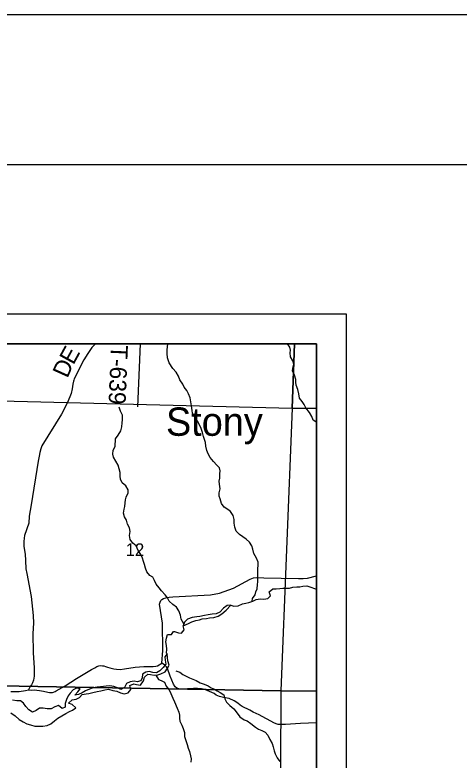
# Model space of a CAD drawing. Extents: x -7.1 to 34, y 0 to 22.
# Drawn here: x 7.891 to 9.377, y 19.508 to 22 of the extents above; entities that cross this region are included whole.
import ezdxf

# ---------------------------------------------------------------- set-up
doc = ezdxf.new("R2010")
doc.units = 0
for name, color, linetype in [('Default', 7, 'Continuous'), ('GM_X_County_Road', 7, 'Continuous'), ('GM_X_Major_Lake', 7, 'Continuous'), ('GM_X_Major_River', 7, 'Continuous'), ('GM_X_Minor_Lake_Text', 7, 'Continuous'), ('GM_X_Minor_River', 7, 'Continuous'), ('GM_X_Section', 7, 'Continuous'), ('GM_X_Section_Text', 7, 'Continuous'), ('GM_X_Township_Road', 7, 'Continuous'), ('GM_X_Township_Road_Text', 7, 'Continuous'), ('SH_Border', 7, 'Continuous'), ('SH_Cut_Line', 7, 'Continuous'), ('SH_Data', 7, 'Continuous')]:
    doc.layers.add(name, color=color, linetype=linetype)

msp = doc.modelspace()

# ---------------------------------------------------------------- linework, layer by layer
at = {"layer": 'Default'}
for points in [[(8.8267, 20.9), (7.8038, 20.9), (7.7992, 20.7106), (8.8192, 20.6854)], [(8.9, 20.684), (8.9, 20.9), (8.8267, 20.9), (8.8192, 20.6854)], [(8.9, 19.7387), (8.9, 20.684), (8.8192, 20.6854), (8.7812, 19.7403)], [(8.9, 18.7216), (8.9, 19.7387), (8.7812, 19.7403), (8.7765, 18.7248)]]:
    msp.add_lwpolyline(points, close=True, dxfattribs=at)
at = {"layer": 'GM_X_County_Road'}
for points in [[(7.9365, 19.7429), (7.9454, 19.7423), (7.9561, 19.7432), (7.9733, 19.7412), (7.987, 19.739), (8.0012, 19.735), (8.0071, 19.7347), (8.0122, 19.7344), (8.0168, 19.7344), (8.0208, 19.7353), (8.0259, 19.7377), (8.0291, 19.7403), (8.0593, 19.757), (8.0976, 19.7806), (8.1476, 19.8113), (8.1589, 19.8171), (8.1654, 19.821), (8.1718, 19.8234), (8.1785, 19.8241), (8.1846, 19.8238), (8.1889, 19.823), (8.1943, 19.8216), (8.2014, 19.8188), (8.2086, 19.8172), (8.2218, 19.8137), (8.2314, 19.8121), (8.2435, 19.8116), (8.2575, 19.8134), (8.294, 19.8193), (8.3222, 19.821), (8.3431, 19.8212), (8.3538, 19.821), (8.3632, 19.8218), (8.3686, 19.8238), (8.3825, 19.8322), (8.3866, 19.8744), (8.3851, 19.9664), (8.3756, 20.0293), (8.3768, 20.0361), (8.3796, 20.0422), (8.3831, 20.0457), (8.3888, 20.0485), (8.3957, 20.0505), (8.4069, 20.0528), (8.4193, 20.0537), (8.5455, 20.0611), (8.5763, 20.0661), (8.6231, 20.0836), (8.6787, 20.1133), (8.6897, 20.1174), (8.6983, 20.1187), (8.7245, 20.1174), (8.8396, 20.1149), (8.8558, 20.1156), (8.8698, 20.1167), (8.9, 20.1248)], [(7.8782, 19.7371), (7.9059, 19.7378), (7.9266, 19.7405), (7.9365, 19.7429)]]:
    msp.add_lwpolyline(points, dxfattribs=at)
at = {"layer": 'GM_X_Major_Lake'}
for points in [[(7.8776, 19.6658), (7.8918, 19.6558), (7.9053, 19.6439), (7.9191, 19.6362), (7.9314, 19.6299), (7.944, 19.6256), (7.9577, 19.622), (7.9714, 19.6219), (7.9851, 19.6217), (7.9988, 19.6242), (8.0112, 19.6298), (8.024, 19.6395), (8.0349, 19.648), (8.048, 19.6558), (8.062, 19.6644), (8.0744, 19.6707), (8.0842, 19.675), (8.0947, 19.6835), (8.0824, 19.6943), (8.0701, 19.6987), (8.0833, 19.7095), (8.0958, 19.7116), (8.1078, 19.7175), (8.1168, 19.7275), (8.1293, 19.73), (8.1388, 19.7309), (8.1524, 19.7342), (8.1664, 19.7378), (8.1785, 19.7403), (8.1925, 19.7436), (8.2039, 19.7449), (8.2184, 19.741), (8.2318, 19.7382), (8.2448, 19.7334), (8.2574, 19.7299), (8.2706, 19.7335), (8.2796, 19.7446), (8.2763, 19.7575), (8.2888, 19.7634), (8.2983, 19.7609), (8.3113, 19.7592), (8.3221, 19.7727), (8.3249, 19.786), (8.3357, 19.796), (8.3453, 19.7939), (8.3575, 19.7918), (8.37, 19.7932), (8.3798, 19.7964), (8.3941, 19.8038), (8.4015, 19.8161), (8.4071, 19.8257), (8.4027, 19.8396), (8.4021, 19.8518), (8.4004, 19.8639)], [(8.4004, 19.8639), (8.3926, 19.8539), (8.3939, 19.8425), (8.3964, 19.8289), (8.3878, 19.8181), (8.3762, 19.807), (8.3646, 19.7999), (8.3524, 19.8012), (8.3405, 19.8041), (8.3299, 19.8024), (8.3186, 19.7954), (8.3166, 19.7832), (8.3129, 19.7737), (8.3001, 19.77), (8.2905, 19.7725), (8.2772, 19.7704), (8.2648, 19.7641), (8.2582, 19.7515), (8.2454, 19.7441), (8.235, 19.7496), (8.222, 19.7539), (8.2091, 19.7564), (8.1969, 19.7558), (8.1874, 19.7545), (8.1772, 19.7536), (8.1669, 19.7522)], [(8.1167, 19.7332), (8.1042, 19.7273), (8.0913, 19.7256), (8.1014, 19.7367), (8.1092, 19.7463), (8.0978, 19.7484), (8.0857, 19.7437), (8.076, 19.7325), (8.0697, 19.7229), (8.0635, 19.7107), (8.0591, 19.6977), (8.0593, 19.6852), (8.0491, 19.6805), (8.0376, 19.6905), (8.0247, 19.6858), (8.0123, 19.6791), (7.999, 19.6796), (7.986, 19.6821), (7.9735, 19.6819), (7.963, 19.6745), (7.9501, 19.669), (7.9382, 19.676), (7.9281, 19.6876), (7.92, 19.6988), (7.9103, 19.7062), (7.8974, 19.7068), (7.8837, 19.7081)], [(8.1669, 19.7522), (8.1529, 19.7497), (8.1404, 19.7454), (8.1276, 19.7394), (8.1167, 19.7332)]]:
    msp.add_lwpolyline(points, dxfattribs=at)
at = {"layer": 'GM_X_Major_River'}
for points in [[(8.6136, 20.0266), (8.6242, 20.0234), (8.6386, 20.0237), (8.6529, 20.0308), (8.6642, 20.033), (8.674, 20.0347), (8.6868, 20.0395), (8.698, 20.0451), (8.7116, 20.0469), (8.7241, 20.046), (8.737, 20.0486), (8.7466, 20.0579), (8.7422, 20.071), (8.7541, 20.0808), (8.7654, 20.0814), (8.7779, 20.0816), (8.7878, 20.0826), (8.8097, 20.0831), (8.8214, 20.086), (8.835, 20.0878), (8.8449, 20.088), (8.8547, 20.0897), (8.8679, 20.0908), (8.8809, 20.0865), (8.8935, 20.0818), (8.9, 20.0797)], [(8.4544, 19.9573), (8.472, 19.9655), (8.4827, 19.9707), (8.4964, 19.9747), (8.5084, 19.9772), (8.5182, 19.9808), (8.5321, 19.9818), (8.5423, 19.9835), (8.5571, 19.9849), (8.5714, 19.9893), (8.5837, 19.9975), (8.5979, 20.0091), (8.6136, 20.0266)], [(8.6136, 20.0266), (8.6015, 20.0256), (8.5892, 20.0162), (8.5769, 20.0031), (8.5642, 19.9971), (8.5513, 19.9957), (8.5377, 19.9943), (8.5257, 19.9914), (8.5102, 19.9888), (8.4996, 19.9878), (8.4849, 19.9848), (8.4683, 19.9792), (8.4583, 19.9695), (8.4544, 19.9573)], [(8.4004, 19.8639), (8.3988, 19.8658), (8.3994, 19.8787), (8.3984, 19.8919), (8.3963, 19.9036), (8.398, 19.9158), (8.4023, 19.9284), (8.4156, 19.9282), (8.4215, 19.9386)], [(8.4215, 19.9386), (8.4256, 19.9385), (8.439, 19.9334), (8.4485, 19.9321), (8.4577, 19.9437), (8.4544, 19.9573)]]:
    msp.add_lwpolyline(points, dxfattribs=at)
at = {"layer": 'GM_X_Minor_River'}
for points in [[(8.407, 20.837), (8.4019, 20.8537), (8.401, 20.8673), (8.4009, 20.8799), (8.4016, 20.8897), (8.4026, 20.9)], [(8.9, 20.6374), (8.8982, 20.6389), (8.8886, 20.6448), (8.8846, 20.6576), (8.8764, 20.6704), (8.8641, 20.6857), (8.8586, 20.6974), (8.852, 20.7075), (8.8431, 20.7187), (8.8409, 20.7327), (8.8376, 20.7478), (8.8325, 20.7617), (8.8308, 20.772), (8.831, 20.7814), (8.827, 20.7958), (8.8203, 20.8097), (8.8216, 20.8192), (8.8248, 20.8321), (8.8216, 20.8438), (8.813, 20.8562), (8.8117, 20.8698), (8.813, 20.8793), (8.8106, 20.8895), (8.8028, 20.9)], [(8.6855, 20.0391), (8.6866, 20.0481), (8.6954, 20.0604), (8.6968, 20.0707), (8.7019, 20.0806), (8.7032, 20.095), (8.7038, 20.1045), (8.704, 20.114), (8.7042, 20.1243), (8.7044, 20.1349), (8.7038, 20.147), (8.7054, 20.161), (8.7053, 20.1705), (8.7001, 20.1837), (8.6908, 20.1995), (8.6868, 20.213), (8.6835, 20.2251), (8.6761, 20.2367), (8.6646, 20.2464), (8.6535, 20.2549), (8.6424, 20.2623), (8.6312, 20.2742), (8.6272, 20.2867), (8.6254, 20.3003), (8.6248, 20.3128), (8.6212, 20.3256), (8.613, 20.3391), (8.6034, 20.3465), (8.5912, 20.3539), (8.5823, 20.3663), (8.5775, 20.3814), (8.5747, 20.3912), (8.5752, 20.4018), (8.5777, 20.4151), (8.5762, 20.4314), (8.5749, 20.4412), (8.5774, 20.4507), (8.5772, 20.4651), (8.5785, 20.4754), (8.5753, 20.4852), (8.5668, 20.4949), (8.556, 20.5072), (8.5448, 20.5203), (8.5374, 20.5327), (8.5334, 20.5436), (8.5305, 20.5579), (8.5288, 20.5704), (8.5256, 20.5806), (8.522, 20.5908), (8.5191, 20.6036), (8.5144, 20.6172), (8.5088, 20.6296), (8.5022, 20.642), (8.4932, 20.6559), (8.4855, 20.6679), (8.4838, 20.6777), (8.4824, 20.6924), (8.4803, 20.7061), (8.4781, 20.7193), (8.4722, 20.7324), (8.4667, 20.7437), (8.4578, 20.7557), (8.4527, 20.7655), (8.4434, 20.7793), (8.4383, 20.7918), (8.4309, 20.8053), (8.4193, 20.818), (8.407, 20.837)], [(8.4194, 20.0288), (8.4072, 20.0401), (8.4021, 20.0506), (8.3941, 20.0608), (8.3822, 20.074), (8.3737, 20.0842), (8.3634, 20.097), (8.3583, 20.1087), (8.3529, 20.1196), (8.3426, 20.126), (8.3326, 20.1377), (8.328, 20.1498), (8.3244, 20.1623), (8.3217, 20.1721), (8.3178, 20.1834), (8.3127, 20.1955), (8.3039, 20.2095), (8.2973, 20.2246), (8.2858, 20.2336), (8.277, 20.2457), (8.2742, 20.2597), (8.2764, 20.273), (8.2743, 20.2851), (8.2682, 20.2968), (8.2642, 20.3101), (8.2577, 20.3221), (8.2545, 20.3339), (8.2567, 20.3472), (8.2593, 20.3567), (8.2603, 20.3681), (8.2614, 20.3783), (8.2639, 20.3878), (8.2703, 20.4015), (8.2706, 20.4118), (8.2625, 20.425), (8.2506, 20.4355), (8.2444, 20.4472), (8.2432, 20.4578), (8.2431, 20.4703), (8.2399, 20.4817), (8.2364, 20.4942), (8.2291, 20.5081), (8.221, 20.5206), (8.2186, 20.5308), (8.2196, 20.5441), (8.2264, 20.5571), (8.2284, 20.5821), (8.2367, 20.5951), (8.2457, 20.6092), (8.2493, 20.6225), (8.25, 20.6358), (8.2514, 20.6464), (8.2509, 20.6616), (8.2447, 20.6752), (8.2396, 20.6888)], [(8.4564, 19.9635), (8.4481, 19.98), (8.4453, 19.9928), (8.4401, 20.0075), (8.4319, 20.0199), (8.4194, 20.0288)], [(8.3626, 19.7924), (8.3715, 19.7772), (8.381, 19.7747), (8.3921, 19.7687), (8.3971, 19.7555), (8.4071, 19.7426), (8.4133, 19.7306), (8.4195, 19.7158), (8.4249, 19.703)], [(8.4295, 19.8072), (8.4429, 19.8025), (8.4536, 19.7947), (8.4643, 19.7884), (8.4758, 19.7837), (8.4864, 19.779), (8.4975, 19.7742), (8.5113, 19.7661), (8.5246, 19.7626), (8.5376, 19.756), (8.5475, 19.7497), (8.5586, 19.7453), (8.5681, 19.7394), (8.5777, 19.7347), (8.5899, 19.7262), (8.5939, 19.713), (8.5987, 19.7024), (8.6102, 19.6912), (8.6237, 19.6793), (8.6353, 19.6648), (8.6442, 19.6528), (8.658, 19.6428), (8.6679, 19.6392), (8.6809, 19.631), (8.6959, 19.6188), (8.7062, 19.6121), (8.7176, 19.607), (8.7287, 19.6012), (8.7372, 19.5914), (8.7443, 19.5772), (8.7517, 19.5636), (8.7557, 19.5531), (8.7589, 19.5391), (8.7621, 19.5293), (8.7692, 19.5158), (8.7781, 19.5038)], [(8.4249, 19.703), (8.434, 19.6814), (8.4403, 19.6682), (8.4423, 19.6584), (8.4425, 19.6482), (8.4434, 19.6383), (8.4497, 19.6248), (8.4548, 19.6143), (8.4585, 19.6003), (8.4591, 19.5874), (8.4627, 19.5742), (8.4671, 19.5606), (8.4711, 19.5482), (8.4751, 19.5373), (8.4791, 19.5222), (8.4808, 19.512), (8.4802, 19.5017)]]:
    msp.add_lwpolyline(points, dxfattribs=at)
at = {"layer": 'GM_X_Section'}
for points in [[(8.8192, 20.6854), (8.7812, 19.7403), (7.7801, 19.7571), (7.7992, 20.7106)], [(7.7801, 19.7571), (8.7812, 19.7403), (8.7765, 18.7248), (7.7545, 18.7512)]]:
    msp.add_lwpolyline(points, close=True, dxfattribs=at)
at = {"layer": 'GM_X_Township_Road'}
msp.add_line((8.3105, 20.9), (8.3019, 20.6898), dxfattribs=at)
msp.add_lwpolyline([(8.9, 17.7079), (8.9, 20.9), (6.7921, 20.9), (6.7882, 20.743), (6.7613, 19.7723), (6.7479, 19.0295), (6.7433, 18.7732), (6.7254, 18.1319), (6.7118, 17.7486), (7.7202, 17.7285), (8.4472, 17.7189), (8.6668, 17.7136)], close=True, dxfattribs=at)
for points in [[(8.1612, 20.9), (8.1562, 20.8958), (8.1492, 20.8875), (8.1358, 20.8683), (8.1222, 20.8464), (8.0989, 20.8013), (8.0947, 20.7934), (8.0898, 20.783), (8.0888, 20.7791)], [(8.0888, 20.7791), (8.0877, 20.7752), (8.0855, 20.7655), (8.0825, 20.7497), (8.0793, 20.7335), (8.0675, 20.7034), (8.0469, 20.6647), (7.9818, 20.5589), (7.9779, 20.549), (7.9745, 20.5368), (7.9726, 20.5243), (7.9689, 20.5081), (7.9457, 20.3615), (7.9392, 20.3234), (7.9376, 20.3008), (7.9239, 20.2595), (7.9223, 20.2507), (7.921, 20.2391), (7.921, 20.2225), (7.9254, 20.1972), (7.9271, 20.1754), (7.9281, 20.1478), (7.931, 20.132), (7.9461, 20.0548), (7.9525, 19.9918), (7.9531, 19.9664), (7.9516, 19.9317), (7.9528, 19.867), (7.9554, 19.8163), (7.9555, 19.7887), (7.9539, 19.775), (7.9506, 19.7663), (7.9472, 19.7602), (7.9423, 19.7538), (7.9365, 19.7429)], [(8.9, 19.633), (8.8463, 19.6311), (8.7968, 19.6269), (8.772, 19.6269), (8.7653, 19.6296), (8.7578, 19.6328), (8.7479, 19.6383), (8.7188, 19.6542), (8.7085, 19.6599), (8.6889, 19.6684), (8.6771, 19.6757), (8.6513, 19.6873), (8.6452, 19.6921), (8.6367, 19.6987), (8.6253, 19.7065), (8.6077, 19.7137), (8.5897, 19.7176), (8.5753, 19.7204), (8.5651, 19.7249), (8.5575, 19.7306), (8.5269, 19.7447), (8.5154, 19.7465), (8.5024, 19.7471), (8.4886, 19.7476), (8.4484, 19.7449), (8.4398, 19.7463), (8.433, 19.7492), (8.428, 19.7531), (8.4214, 19.7617), (8.411, 19.7893), (8.4023, 19.8142), (8.3983, 19.8205), (8.392, 19.8264), (8.3825, 19.8322)]]:
    msp.add_lwpolyline(points, dxfattribs=at)
at = {"layer": 'SH_Border'}
msp.add_lwpolyline([(1.5, 21.5), (33.5, 21.5), (33.5, 0.5), (1.5, 0.5)], close=True, dxfattribs=at)
at = {"layer": 'SH_Cut_Line'}
for points in [[(0, 0), (34, 0), (34, 22), (0, 22)], [(8.9, 17.7079), (8.9, 20.9), (2.1, 20.9), (2.1, 17.7253), (2.5551, 17.7155), (2.7886, 17.7105), (3.0659, 17.6986), (3.7215, 17.6707), (3.8238, 17.6717), (3.8304, 17.7952), (4.3, 17.7873), (4.5657, 17.7857), (4.7094, 17.7848), (5.0443, 17.7832), (5.0544, 17.7831), (5.1115, 17.7819), (5.5047, 17.7737), (5.7514, 17.7685), (6.1904, 17.7592), (6.3575, 17.7557), (6.7118, 17.7486), (7.7202, 17.7285), (8.4472, 17.7189), (8.6668, 17.7136)]]:
    msp.add_lwpolyline(points, close=True, dxfattribs=at)
at = {"layer": 'SH_Data'}
for p, q in [((2, 21), (9, 21)), ((9, 21), (9, 14)), ((2.1, 20.9), (8.9, 20.9)), ((8.9, 20.9), (8.9, 14.1))]:
    msp.add_line(p, q, dxfattribs=at)

# ---------------------------------------------------------------- texts
at = {"layer": 'GM_X_Minor_Lake_Text'}
msp.add_text('Stony', height=0.09471, rotation=359.9755, dxfattribs=at).set_placement((8.3968, 20.5926))
at = {"layer": 'GM_X_Section_Text'}
msp.add_text('12', height=0.04186, rotation=0, dxfattribs=at).set_placement((8.2619, 20.1911))
at = {"layer": 'GM_X_Township_Road_Text'}
for s, height, rotation, p in [('E', 0.0568, 61.2715, (8.0869, 20.8273)), ('T-639', 0.05682, 267.6418, (8.2128, 20.8967)), ('D', 0.0568, 65.7619, (8.0668, 20.7828))]:
    msp.add_text(s, height=height, rotation=rotation, dxfattribs=at).set_placement(p)

doc.saveas('drawing.dxf')
